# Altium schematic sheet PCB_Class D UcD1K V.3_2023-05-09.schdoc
size 449 x 152 mm
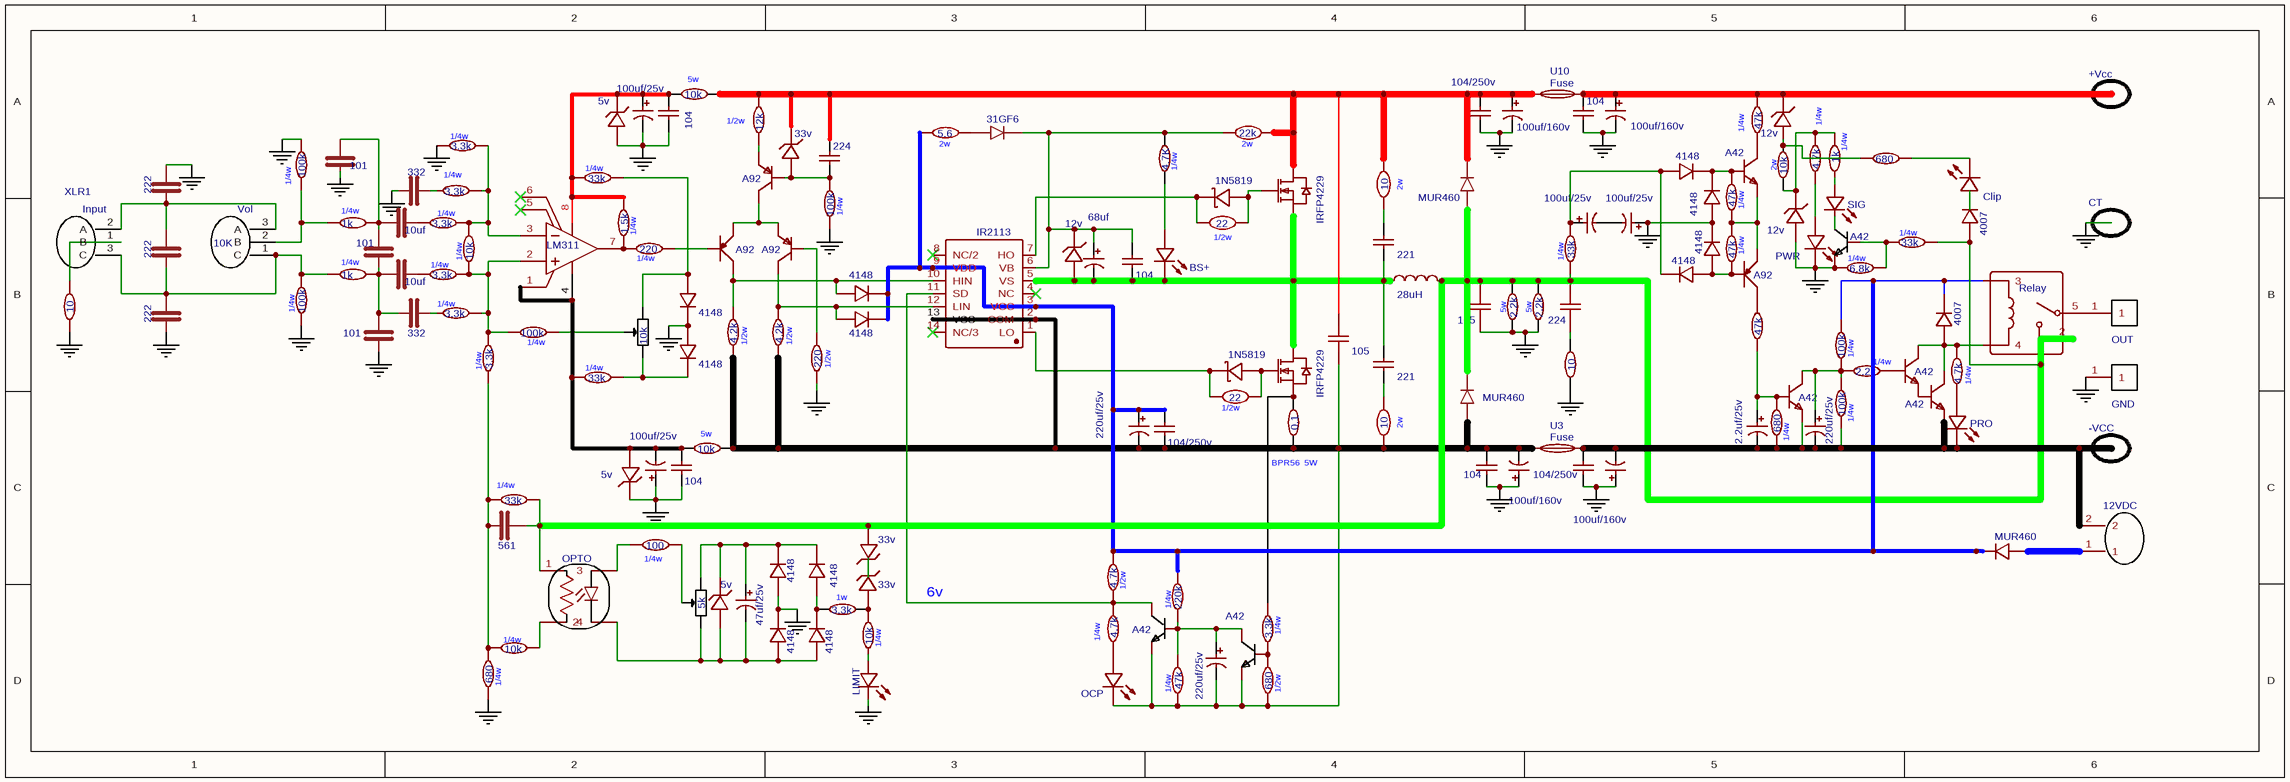
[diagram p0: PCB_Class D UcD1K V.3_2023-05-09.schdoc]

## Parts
10K  Vol  [JST 3P]
30UH  28uH  [TOROID CORE]
+100V  +Vcc  [FASTON TAB]
-100V  -VCC  [FASTON TAB]
C1  105  [CAP MYLAR 22MM]
C2  104  [MYLAR CAP 10MM]
C3  100uf/160v  [CAP-TH_BD16.0-P7.50-D1.2-FD]
C4  224  [MYLAR CAP 10MM]
C5  332  [CERCAP]
C6  101  [CERCAP]
C7  332  [CERCAP]
C8  10uf  [NONPOLAR CAP 22UF]
C9  101  [CERCAP]
C10  101  [CERCAP]
C11  222  [CERCAP]
C12  222  [CERCAP]
C13  222  [CERCAP]
C14  224  [CAP-CBB-18.5*8.5]
C15  561  [CERCAP]
C16  220uf/25v  [CAP-TH_BD6.3-P2.50-D1.0-FD]
C17  220uf/25v  [CAP-TH_BD6.3-P2.50-D1.0-FD]
C18  104/250v  [POLYCAP104]
C19  47uf/25v  [CAP-TH_BD6.3-P2.50-D1.0-FD]
C20  100uf/25v  [CAP-TH_BD6.3-P2.50-D1.0-FD]
C21  100uf/25v  [CAP-TH_BD6.3-P2.50-D1.0-FD]
C22  104  [MYLAR CAP 10MM]
C23  100uf/160v  [CAP-TH_BD16.0-P7.50-D1.2-FD]
C24  68uf  [CAP-TH_BD6.3-P2.50-D1.0-FD]
C25  104  [POLYCAP104]
C26  2.2uf/25v  [CAP-TH_BD6.3-P2.50-D1.0-FD]
C27  104/250v  [MYLAR CAP 10MM]
C28  100uf/160v  [CAP-TH_BD16.0-P7.50-D1.2-FD]
C29  220uf/25v  [CAP-TH_BD6.3-P2.50-D1.0-FD]
C32  105  [CAP MYLAR 22MM]
C37  10uf  [NONPOLAR CAP 22UF]
C39  100uf/25v  [CAP-TH_BD6.3-P2.50-D1.0-FD]
C40  104  [POLYCAP104]
C41  221  [WIMA RED]
C42  221  [WIMA RED]
C43  100uf/25v  [CAP-TH_BD6.3-P2.50-D1.0-FD]
C44  100uf/160v  [CAP-TH_BD16.0-P7.50-D1.2-FD]
C45  104/250v  [MYLAR CAP 10MM]
C46  104  [POLYCAP104]
D1  MUR460  [MUR460R]
D2  4148  [DO-35R]
D3  4148  [DO-35R]
D4  1N5819  [DO-41_BD2.4-L4.7-P8.70-D0.9-FD]
D5  4148  [DO-35R]
D6  MUR460  [MUR460R]
D7  5v  [DO-35R]
D8  33v  [DO-35R]
D9  4148  [DO-35R]
D10  4148  [DO-35R]
D11  12v  [DO-35R]
D12  31GF6  [DO-201_BD5.3-L9.5-P13.50-D1.4-FD]
D13  4148  [DO-35R]
D14  4148  [DO-35R]
D15  1N5819  [DO-41_BD2.4-L4.7-P8.70-D0.9-FD]
D16  33v  [DO-35R]
D17  33v  [DO-35R]
D18  4148  [DO-35R]
D19  4148  [DO-35R]
D20  4148  [DO-35R]
D21  4148  [DO-35R]
D22  MUR460  [MUR460R]
D23  4148  [DO-35R]
D24  4007  [1N4007R]
D25  12v  [DO-35R]
D26  12v  [DO-35R]
D27  4007  [1N4007R]
D30  5v  [DO-35R]
D31  5v  [DO-35R]
DCO  10k  [RES-ADJ-TH_3296W]
GND  CT  [FASTON TAB]
LED1  BS+  [LED B 5MM]
LIMITER  5k  [RES-ADJ-TH_3296W]
P1  12VDC  [CONN-TH_2P-P5.00_WJ300V-5.00-2P]
P2  OUT  [FASTON TAB]
P4  GND  [FASTON TAB]
Q1  IRFP4229  [TO-247L]
Q2  IRFP4229  [TO-247L]
Q3  A92  [TO-92-3_L4.8-W3.7-P2.54-R]
Q4  A92  [TO-92-3_L4.8-W3.7-P2.54-R]
Q5  A42  [TO-92-3_L4.8-W3.7-P2.54-R]
Q6  A92  [TO-92-3_L4.8-W3.7-P2.54-R]
Q7  A92  [TO-92-3_L4.8-W3.7-P2.54-R]
Q8  A42  [TO-92-3_L4.8-W3.7-P2.54-R]
Q9  A42  [TO-92-3_L4.8-W3.7-P2.54-R]
Q10  A42  [TO-92-3_L4.8-W3.7-P2.54-R]
Q27  A42  [TO-92-3_L4.8-W3.7-P2.54-R]
Q28  A42  [TO-92-3_L4.8-W3.7-P2.54-R]
Q29  A42  [TO-92-3_L4.8-W3.7-P2.54-R]
R1  22  [AXIAL-0.4R]
R2  220  [AXIAL-0.3R]
R3  4.2k  [AXIAL-0.5 R]
R4  12k  [AXIAL-0.5 R]
R5  100k  [AXIAL-0.3R]
R6  220  [AXIAL-0.3R]
R7  22k  [AXIAL-0.7]
R8  10k  [5WATTS RESISTOR]
R9  1.5k  [AXIAL-0.3R]
R10  33k  [AXIAL-0.3R]
R11  33k  [AXIAL-0.3R]
R12  100k  [AXIAL-0.3R]
R13  3.3k  [AXIAL-0.3R]
R14  2.2k  [5WATTS RESISTOR]
R15  3.3k  [AXIAL-0.3R]
R16  3.3k  [AXIAL-0.3R]
R17  3.3k  [AXIAL-0.3R]
R18  3.3k  [AXIAL-0.3R]
R19  3.3k  [AXIAL-0.3R]
R20  1k  [AXIAL-0.3R]
R21  1k  [AXIAL-0.3R]
R22  100k  [AXIAL-0.3R]
R23  10  [5WATTS RESISTOR]
R24  680  [AXIAL-0.4R]
R25  100k  [AXIAL-0.3R]
R26  5.6  [AXIAL-0.7]
R27  10  [AXIAL-0.5 R]
R28  33k  [AXIAL-0.3R]
R29  680  [AXIAL-0.3R]
R30  3.3k  [AXIAL-0.3R]
R31  220k  [AXIAL-0.3R]
R32  47k  [AXIAL-0.3R]
R33  4.7k  [AXIAL-0.3R]
R34  22  [AXIAL-0.4R]
R35  4.7k  [AXIAL-0.5 R]
R36  10k  [AXIAL-0.3R]
R37  100  [AXIAL-0.3R]
R38  3.3k  [AXIAL-0.5 R]
R39  10k  [AXIAL-0.3R]
R40  0.1  [BPR56  5W]
R41  4.7K  [AXIAL-0.3R]
R42  LIMIT  [LED R 5MM]
R43  10  [AXIAL-0.7]
R44  10  [AXIAL-0.7]
R45  33k  [AXIAL-0.3R]
R46  4.2k  [AXIAL-0.5 R]
R47  47k  [AXIAL-0.3R]
R48  47k  [AXIAL-0.3R]
R49  47k  [AXIAL-0.3R]
R50  47k  [AXIAL-0.3R]
R51  680  [AXIAL-0.3R]
R52  100k  [AXIAL-0.3R]
R53  2.2k  [5WATTS RESISTOR]
R54  100k  [AXIAL-0.3R]
R55  2.2k  [AXIAL-0.3R]
R56  4.7k  [AXIAL-0.3R]
R57  PRO  [LED R 5MM]
R58  PWR  [LED B 5MM]
R59  6.8k  [AXIAL-0.3R]
R60  SIG  [LED G 5MM]
R61  1k  [AXIAL-0.3R]
R62  4.7k  [AXIAL-0.3R]
R63  33k  [AXIAL-0.3R]
R64  680  [AXIAL-0.5 R]
R65  10k  [AXIAL-0.3R]
R78  10k  [5WATTS RESISTOR]
R81  10k  [AXIAL-0.7]
R126  OCP  [LED R 5MM]
RLY1  Relay  [SLA RELAY 12V]
U1  OPTO  [OPTO]
U2  IR2113  [DIP-14_L19.0-W7.0-P2.54-LS7.6-BL]
U3  Fuse  [FUSE-TH_L22.6-W9.0]
U5  LM311N  [DIP-8R]  (value not drawn)
U10  Fuse  [FUSE-TH_L22.6-W9.0]
XLR1  Input  [JST 3P]
YG1  Clip  [LED YG 5M]

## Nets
GND: C2.2 C3.1 C6.1 C7.1 C10.1 C12.1 C13.2 C21.1 C22.1 C23.2 C27.2 C28.1 C32.1 C39.1 C40.1 C43.2 C44.2 C45.1 C46.1 D3.2 D5.1 D9.2 D13.1 D18.1 D20.2 D25.1(A) D30.2(K) D31.1(A) GND.1 P4.1 Q29.3(E) R2.2 R5.2 R14.1 R18.1 R22.1 R23.1 R25.2 R27.2 R29.1 R42.2(K) R53.1 R58.2(K) R59.1
Net10K_1: 10K.1(C) C11.1 C12.2 R21.1 R22.2 XLR1.3(C)
Net10K_2: 10K.2(B) R20.1 R25.1
Net10K_3: 10K.3(A) C11.2 C13.1 XLR1.2(A)
Net30UH_1: 30UH.1 C24.2 C25.1 C41.1 C42.2 D11.1(A) LED1.2(K) Q1.3(S) Q2.2(D) U2.5(VS)
Net30UH_2: 30UH.2 C14.2 C15.2 C32.2 D1.1(C) D16.1(A) D22.2(A) D27.1(A) R14.2 R28.2 R45.2 R53.2 R63.2 RLY1.2 U1.1
Net+100V_1: +100V.1 C22.2 C23.1 D26.2(K) R49.1 U10.1
Net-100V_1: -100V.1 C26.2 C27.1 C28.2 C29.2 P1.2 Q8.3(E) Q10.3(E) R51.2 R52.2 R57.2(K) U3.1
NetC1_1: C1.1 C2.1 C3.2 C16.2 C17.2 C18.1 D1.2(A) Q5.3(E) Q27.3(E) R3.2 R8.1 R24.1 R32.1 R40.2 R44.1 R46.2 R126.2(K) U2.2(COM) U2.13(VSS) U3.2
NetC1_2: C1.2 C4.2 C44.1 C45.2 D8.2(K) D22.1(C) Q1.2(D) R4.1 R7.1 R43.2 R78.1 U10.2
NetC4_1: C4.1 D8.1(A) Q4.2(B) R5.1
NetC5_1: C5.1 C6.2 C8.2 C9.1 R21.2
NetC5_2: C5.2 R17.1
NetC7_2: C7.2 R16.1
NetC8_1: C8.1 R15.1
NetC9_2: C9.2 C10.2 C37.2 R20.2
NetC14_1: C14.1 R23.2
NetC15_1: C15.1 R19.1 R28.1 R29.2 R36.2
NetC16_1: C16.1 Q5.2(B) Q27.1(C) R31.1 R32.2
NetC17_1: C17.1 C18.2 D2.2 D6.1(C) D19.2 D24.2(K) R26.1 R31.2 R35.2 R54.1 RLY1.3 U2.3(VCC) U2.9(VDD)
NetC19_1: C19.1 D7.2(K) D10.2 D13.2 LIMITER.1(A)
NetC19_2: C19.2 D7.1(A) D9.1 D14.1 LIMITER.3(E) U1.4
NetC20_1: C20.1 D21.1 D23.2 R45.1
NetC20_2: C20.2 C21.2
NetC24_1: C24.1 C25.2 D11.2(K) D12.2(C) R7.2 R41.2 U2.6(VB)
NetC26_1: C26.1 Q8.2(B) R50.2 R51.1
NetC29_1: C29.1 Q8.1(C) R52.1 R54.2 R55.1
NetC37_1: C37.1 R13.1
NetC39_2: C39.2 C40.2 D30.1(A) R8.2 R11.1 U5.1(NC) U5.4(VCC-)
NetC41_2: C41.2 R43.1
NetC42_1: C42.1 R44.2
NetC43_1: C43.1 C46.2 D31.2(K) R9.1 R10.1 R78.2 U5.8(VCC+)
NetD2_1: D2.1 Q3.1 R3.1 U2.10(HIN)
NetD3_1: D3.1 DCO.1(A) R10.2
NetD4_1: D4.1(A) Q2.1(G) R1.2
NetD4_2: D4.2(K) R1.1 U2.1(LO)
NetD5_2: D5.2 DCO.3(E) R11.2
NetD6_2: D6.2(A) P1.1
NetD10_1: D10.1 D14.2 R38.1
NetD12_1: D12.1(A) R26.2
NetD15_1: D15.1(K) R34.1 U2.7(HO)
NetD15_2: D15.2(A) Q1.1(G) R34.2
NetD16_2: D16.2(K) D17.2(K)
NetD17_1: D17.1(A) R38.2 R39.2
NetD18_2: D18.2 D21.2 Q28.2(B) R47.1
NetD19_1: D19.1 Q7.1(C) R46.1 U2.12(LIN)
NetD20_1: D20.1 D23.1 Q6.2 R48.2
NetD24_1: D24.1(A) Q9.1(C) Q10.1(C) R56.1 RLY1.4
NetD25_2: D25.2(K) R61.1 R62.1 R81.1
NetD26_1: D26.1(A) R64.1 R81.2
NetD27_2: D27.2(K) YG1.1(A)
NetDCO_2: DCO.2(S) R12.2
NetLED1_1: LED1.1(A) R41.1
NetLIMITER_2: LIMITER.2(S) R37.1
NetP2_1: P2.1 RLY1.5
NetQ2_3: Q2.3(S) R30.1 R40.1
NetQ3_2: Q3.2 R6.2
NetQ3_3: Q3.3 Q4.1(C) Q7.3(E)
NetQ4_3: Q4.3(E) R4.2
NetQ5_1: Q5.1(C) R33.2 R35.1 U2.11(SD)
NetQ6_1: Q6.1 R50.1
NetQ6_3: Q6.3 Q28.3(E) R47.2 R48.1
NetQ7_2: Q7.2(B) R2.1
NetQ9_2: Q9.2(B) R55.2
NetQ9_3: Q9.3(E) Q10.2(B)
NetQ27_2: Q27.2(B) R24.2 R30.2
NetQ28_1: Q28.1(C) R49.2
NetQ29_1: Q29.1(C) R60.2(K)
NetQ29_2: Q29.2(B) R59.2 R63.1
NetR6_1: R6.1 R9.2 U5.7(OUT)
NetR12_1: R12.1 R15.2 R17.2 R19.2 R65.1 U5.2(IN+)
NetR13_2: R13.2 R16.2 R18.2 R65.2 U5.3(IN-)
NetR27_1: R27.1 XLR1.1(B)
NetR33_1: R33.1 R126.1(A)
NetR36_1: R36.1 U1.2
NetR37_2: R37.2 U1.3
NetR39_1: R39.1 R42.1(A)
NetR56_2: R56.2 R57.1(A)
NetR58_1: R58.1(A) R62.2
NetR60_1: R60.1(A) R61.2
NetR64_2: R64.2 YG1.2(K)

Not connected (* = marked no-connect by the designer): U2 4(NC)* 8(NC/2)* 14(NC/3)*; U5 5(OFFSET_N2)* 6(OFFSET_N1)*

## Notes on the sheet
- (near R78) 5w
- (near R18) 1/4w
- (near R4) 1/2w
- (near R26) 2w
- (near R7) 2w
- (near R49) 1/4w
- 1/4w
- (near R61) 1/4w
- (near R25) 1/4w
- (near R20) 1/4w
- (near R13) 1/4w
- (near R10) 1/4w
- (near R5) 1/4w
- (near R41) 1/4w
- (near R43) 2w
- (near R81) 2w
- (near R21) 1/4w
- (near R15) 1/4w
- (near R65) 1/4w
- (near R6) 1/4w
- (near R34) 1/2w
- (near R45) 1/4w
- (near R63) 1/4w
- (near R22) 1/4w
- (near R12) 1/4w
- (near R3) 1/2w
- (near R46) 1/2w
- (near R53) 5w
- (near R14) 5w
- (near R19) 1/4w
- (near R11) 1/4w
- (near R2) 1/2w
- (near R1) 1/2w
- (near R52) 1/4w
- (near R55) 1/4w
- (near R56) 1/4w
- (near R8) 5w
- (near R40) BPR56  5W
- (near R44) 2w
- (near R51) 1/4w
- (near R28) 1/4w
- (near R37) 1/4w
- (near R38) 1w
- 6v
- (near R35) 1/2w
- (near R36) 1/4w
- (near R39) 1/4w
- (near R33) 1/4w
- (near R30) 1/4w
- (near R29) 1/4w
- (near R32) 1/4w
- (near R24) 1/2w

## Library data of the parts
10K = Vol: BOM_Manufacturer Part: 3 pin header; Contributor: Deimoss
30UH = 28uH: Contributor: manailadorin
+100V = +Vcc: BOM_Manufacturer Part: 19705-4301; Contributor: alexathome1995
-100V = -VCC: BOM_Manufacturer Part: 19705-4301; Contributor: alexathome1995
C1 C32 = 105: BOM_Manufacturer: Winday Elec; BOM_Manufacturer Part: SMPC_105K0250DB2815; nameAlias: Capacitance; Contributor: LCSC
C2 C22 = 104: BOM_Manufacturer: FH; BOM_Manufacturer Part: 1206CG104J500NT; Value: 100nF; Voltage: 50V; Tolerance: ±5%; BOM_EasyEDA: E46348
C3 C23 C28 C44 = 100uf/160v: BOM_Manufacturer: AISHI; BOM_Manufacturer Part: EGD2CM101L20OT; nameAlias: Capacitance
C4 = 224: BOM_Manufacturer: FH; BOM_Manufacturer Part: 1206CG104J500NT; Value: 100nF; Voltage: 50V; Tolerance: ±5%; BOM_EasyEDA: E46348
C14 = 224: BOM_Manufacturer: Winday Elec; BOM_Manufacturer Part: SMPC_105K0250DB2815; nameAlias: Capacitance; Contributor: LCSC
C16 C17 C29 = 220uf/25v: BOM_Manufacturer: Rubycon; BOM_Manufacturer Part: 25TZV100M6.3X8; nameAlias: Capacitance
C18 = 104/250v: BOM_Manufacturer: YAGEO; BOM_Manufacturer Part: CC0805ZRY5V9BB104; nameAlias: Capacitance
C19 = 47uf/25v: BOM_Manufacturer: Rubycon; BOM_Manufacturer Part: 25TZV100M6.3X8; nameAlias: Capacitance
C20 C21 C39 C43 = 100uf/25v: BOM_Manufacturer: Rubycon; BOM_Manufacturer Part: 25TZV100M6.3X8; nameAlias: Capacitance
C24 = 68uf: BOM_Manufacturer: Rubycon; BOM_Manufacturer Part: 25TZV100M6.3X8; nameAlias: Capacitance
C25 C40 C46 = 104: BOM_Manufacturer: YAGEO; BOM_Manufacturer Part: CC0805ZRY5V9BB104; nameAlias: Capacitance
C26 = 2.2uf/25v: BOM_Manufacturer: Rubycon; BOM_Manufacturer Part: 25TZV100M6.3X8; nameAlias: Capacitance
C27 C45 = 104/250v: BOM_Manufacturer: FH; BOM_Manufacturer Part: 1206CG104J500NT; Value: 100nF; Voltage: 50V; Tolerance: ±5%; BOM_EasyEDA: E46348
C41 C42 = 221: BOM_Manufacturer: FH; BOM_Manufacturer Part: 1206CG104J500NT; Value: 100nF; Voltage: 50V; Tolerance: ±5%; BOM_EasyEDA: E46348
D1 D22 = MUR460: BOM_Manufacturer: Jingdao; BOM_Manufacturer Part: ES2DF; Contributor: LCSC; SMT Type: Extend
D2 D3 D5 D9 D10 D13 D14 D18-D21 D23 = 4148: BOM_Manufacturer: BLUE ROCKET; BOM_Manufacturer Part: 1N4007W; Contributor: LCEDA_Lib
D4 D15 = 1N5819: BOM_Manufacturer: KEXIN; BOM_Manufacturer Part: 1N5819W; Contributor: LCSC; SMT Type: Extend
D6 = MUR460: BOM_Manufacturer: PANJIT; BOM_Manufacturer Part: 1N4007; Contributor: LCSC
D7 D30 D31 = 5v: BOM_Manufacturer: MDD; BOM_Manufacturer Part: BZT52C12; Contributor: LCSC; SMT Type: Extend
D8 D16 D17 = 33v: BOM_Manufacturer: MDD; BOM_Manufacturer Part: BZT52C12; Contributor: LCSC; SMT Type: Extend
D11 D25 D26 = 12v: BOM_Manufacturer: MDD; BOM_Manufacturer Part: BZT52C12; Contributor: LCSC; SMT Type: Extend
D12 = 31GF6: BOM_Manufacturer: Jingdao; BOM_Manufacturer Part: ES2DF; Contributor: LCSC; SMT Type: Extend
D24 D27 = 4007: BOM_Manufacturer: SEMTECH; BOM_Manufacturer Part: 1N4448
DCO = 10k: Contributor: ryan abubo
GND = CT: BOM_Manufacturer Part: 19705-4301; Contributor: alexathome1995
LED1 = BS+: BOM_Manufacturer: NATIONSTAR; BOM_Manufacturer Part: FC-A2012BK-470H2; SMT Type: Extend
LIMITER = 5k: Contributor: ryan abubo
P1 = 12VDC: BOM_Manufacturer: ReliaPro; BOM_Manufacturer Part: WJ300V-5.0-2P
P2 = OUT: Contributor: juangiraldo04
P4 = GND: Contributor: juangiraldo04
Q1 Q2 = IRFP4229: BOM_Manufacturer: Nexperia; BOM_Manufacturer Part: 2N7002,215; SMT Type: Extend; Contributor: LCEDA_Lib
Q3 Q6 = A92: Contributor: ryan abubo
Q4 Q7 = A92: BOM_Manufacturer: LGE; BOM_Manufacturer Part: BC556B; Contributor: LCSC
Q8-Q10 Q28 = A42: BOM_Manufacturer: KEC; BOM_Manufacturer Part: 2n3904S-RTK/PS; SMT Type: SOT-23; Contributor: LCEDA_Lib
R1 R34 = 22: BOM_Manufacturer: Viking Tech; BOM_Manufacturer Part: CR-06JA7---10R; nameAlias: Resistance (Ohms); Contributor: LCSC
R2 R6 = 220: BOM_Manufacturer: YAGEO; BOM_Manufacturer Part: RC0805FR-074K7L; nameAlias: Resistance (Ohms)
R3 R46 = 4.2k: BOM_Manufacturer: YAGEO; BOM_Manufacturer Part: RC0805FR-074K7L; nameAlias: Resistance (Ohms)
R4 = 12k: BOM_Manufacturer: YAGEO; BOM_Manufacturer Part: RC0805FR-074K7L; nameAlias: Resistance (Ohms)
R5 R12 R22 R25 R52 R54 = 100k: BOM_Manufacturer: YAGEO; BOM_Manufacturer Part: RC0805FR-074K7L; nameAlias: Resistance (Ohms)
R7 = 22k: nameAlias: Value(Ω)
R8 R78 = 10k: BOM_Manufacturer: YAGEO; BOM_Manufacturer Part: MFR3WSFTE73-4K3; nameAlias: Resistance (Ohms)
R9 = 1.5k: BOM_Manufacturer: YAGEO; BOM_Manufacturer Part: RC0805FR-074K7L; nameAlias: Resistance (Ohms)
R10 R11 R28 R45 R63 = 33k: BOM_Manufacturer: YAGEO; BOM_Manufacturer Part: RC0805FR-074K7L; nameAlias: Resistance (Ohms)
R13 R15-R19 R30 R38 = 3.3k: BOM_Manufacturer: YAGEO; BOM_Manufacturer Part: RC0805FR-074K7L; nameAlias: Resistance (Ohms)
R14 R53 = 2.2k: BOM_Manufacturer: YAGEO; BOM_Manufacturer Part: MFR3WSFTE73-4K3; nameAlias: Resistance (Ohms)
R20 R21 R61 = 1k: BOM_Manufacturer: YAGEO; BOM_Manufacturer Part: RC0805FR-074K7L; nameAlias: Resistance (Ohms)
R23 = 10: BOM_Manufacturer: YAGEO; BOM_Manufacturer Part: MFR3WSFTE73-4K3; nameAlias: Resistance (Ohms)
R24 = 680: BOM_Manufacturer: Ever Ohms Tech; BOM_Manufacturer Part: CR2512J4R7E04; nameAlias: Resistance (Ohms); Contributor: LCSC
R26 = 5.6: BOM_Manufacturer: Ever Ohms Tech; BOM_Manufacturer Part: CR2512J4R7E04; nameAlias: Resistance (Ohms); Contributor: LCSC
R27 = 10: BOM_Manufacturer: YAGEO; BOM_Manufacturer Part: RC0805FR-074K7L; nameAlias: Resistance (Ohms)
R29 R51 R64 = 680: BOM_Manufacturer: YAGEO; BOM_Manufacturer Part: RC0805FR-074K7L; nameAlias: Resistance (Ohms)
R31 = 220k: BOM_Manufacturer: Ever Ohms Tech; BOM_Manufacturer Part: CR2512J4R7E04; nameAlias: Resistance (Ohms); Contributor: LCSC
R32 = 47k: BOM_Manufacturer: Ever Ohms Tech; BOM_Manufacturer Part: CR2512J4R7E04; nameAlias: Resistance (Ohms); Contributor: LCSC
R33 R35 = 4.7k: BOM_Manufacturer: Ever Ohms Tech; BOM_Manufacturer Part: CR2512J4R7E04; nameAlias: Resistance (Ohms); Contributor: LCSC
R36 R39 R65 R81 = 10k: BOM_Manufacturer: YAGEO; BOM_Manufacturer Part: RC0805FR-074K7L; nameAlias: Resistance (Ohms)
R37 = 100: BOM_Manufacturer: YAGEO; BOM_Manufacturer Part: RC0805FR-074K7L; nameAlias: Resistance (Ohms)
R40 = 0.1: BOM_Manufacturer: YAGEO; BOM_Manufacturer Part: RC0805FR-074K7L; nameAlias: Resistance (Ohms)
R41 = 4.7K: BOM_Manufacturer: YAGEO; BOM_Manufacturer Part: RC0805FR-074K7L; nameAlias: Resistance (Ohms)
R42 = LIMIT: BOM_Manufacturer: EVERLIGHT; BOM_Manufacturer Part: 204-10SURD/S530-A3
R43 R44 = 10: nameAlias: Value(Ω)
R47-R50 = 47k: BOM_Manufacturer: YAGEO; BOM_Manufacturer Part: RC0805FR-074K7L; nameAlias: Resistance (Ohms)
R55 = 2.2k: BOM_Manufacturer: YAGEO; BOM_Manufacturer Part: RC0805FR-074K7L; nameAlias: Resistance (Ohms)
R56 R62 = 4.7k: BOM_Manufacturer: YAGEO; BOM_Manufacturer Part: RC0805FR-074K7L; nameAlias: Resistance (Ohms)
R57 = PRO: BOM_Manufacturer: EVERLIGHT; BOM_Manufacturer Part: 204-10SURD/S530-A3
R58 = PWR: BOM_Manufacturer: EVERLIGHT; BOM_Manufacturer Part: 204-10SURD/S530-A3
R59 = 6.8k: BOM_Manufacturer: YAGEO; BOM_Manufacturer Part: RC0805FR-074K7L; nameAlias: Resistance (Ohms)
R60 = SIG: BOM_Manufacturer: EVERLIGHT; BOM_Manufacturer Part: 204-10SURD/S530-A3
R126 = OCP: BOM_Manufacturer: EVERLIGHT; BOM_Manufacturer Part: 204-10SURD/S530-A3
RLY1 = Relay: BOM_Manufacturer: SONGLE; BOM_Manufacturer Part: SLA-24VDC-SL-A
U1 = OPTO: Contributor: ryan abubo
U2 = IR2113: BOM_Manufacturer: IR; BOM_Manufacturer Part: IR2113PBF
U3 U10 = Fuse: BOM_Manufacturer: XCFuse; BOM_Manufacturer Part: 7A 250VACGlass tube fuse
U5 = LM311N: Contributor: abuboryan85
XLR1 = Input: BOM_Manufacturer Part: 3 pin header; Contributor: Deimoss
YG1 = Clip: BOM_Manufacturer: EVERLIGHT; BOM_Manufacturer Part: 204-10SURD/S530-A3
